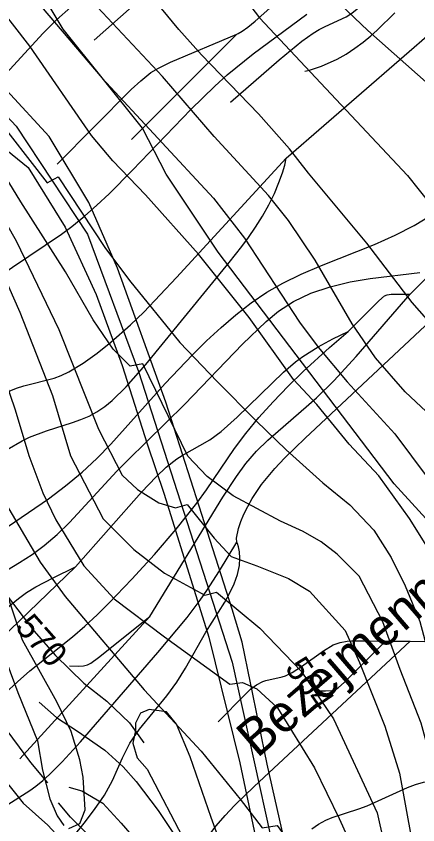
# Model space of a CAD drawing. Extents: x -709584 to -702006, y -1161789 to -1157496.
# Drawn here: x -707846 to -707683.9, y -1159256.1 to -1158929.8 of the extents above; entities that cross this region are included whole.
import ezdxf

# ---------------------------------------------------------------- set-up
doc = ezdxf.new("R2010")
doc.units = 0
for name, color, linetype in [('110_silnice II. třídy a III. třídy', 7, 'Continuous'), ('120_vrstevnice hlavní', 7, 'Continuous'), ('121_vrstevnice hlavní_popis', 7, 'Continuous'), ('122_vrstevnice základní', 7, 'Continuous'), ('408_BPEJ_linie', 7, 'Continuous'), ('411_akumulovaný odtok', 7, 'Continuous'), ('419_LPIS PB', 7, 'Continuous'), ('502_vodní tok_popis', 7, 'Continuous')]:
    doc.layers.add(name, color=color, linetype=linetype)

msp = doc.modelspace()

# ---------------------------------------------------------------- linework, layer by layer
at = {"layer": '110_silnice II. třídy a III. třídy'}
msp.add_lwpolyline([(-707891.2, -1158926.02), (-707845.98, -1158974.16), (-707817.26, -1159017.7), (-707796.68, -1159073.19), (-707758.86, -1159190.4), (-707734.44, -1159300.73), (-707726.3, -1159328.96), (-707710.98, -1159361.01), (-707689.44, -1159398.33), (-707672.68, -1159420.33), (-707591.22, -1159519.21), (-707503.14, -1159616.33), (-707475.85, -1159642.64), (-707378.49, -1159735.32), (-707320.09, -1159789.38), (-707255.46, -1159826.22), (-707200.25, -1159861.16), (-707169.1, -1159885.49), (-707119.45, -1159925.38), (-707100.71, -1159937.16)], dxfattribs=at)
at = {"layer": '120_vrstevnice hlavní'}
for points in [[(-707636.08, -1159108.46), (-707639.17, -1159101.31), (-707643.74, -1159093.3), (-707658.02, -1159076.3), (-707672.31, -1159061.02), (-707686.17, -1159045.3), (-707704.45, -1159021.3), (-707728.03, -1158993.16), (-707735.74, -1158983.3), (-707748.17, -1158969.16), (-707771.17, -1158945.3), (-707780.31, -1158935.15), (-707815.32, -1158892.58)], [(-707674.29, -1159261.8), (-707677.87, -1159232.35), (-707682.54, -1159215.05), (-707691.03, -1159193.35), (-707697.97, -1159174.23), (-707707.61, -1159155.78), (-707716.48, -1159146.83), (-707722.87, -1159141.85), (-707730.12, -1159137.73), (-707739.27, -1159133.61), (-707758.43, -1159123.31), (-707768.96, -1159115.58), (-707776.73, -1159107.32), (-707794.94, -1159070.03), (-707799.98, -1159071.07), (-707806.9, -1159064.2), (-707814.95, -1159052.25), (-707826.02, -1159032.96), (-707844.09, -1159004.73), (-707859.8, -1158979.14)], [(-707861.24, -1159145.22), (-707849.59, -1159163.75), (-707838.9, -1159177.82), (-707830.11, -1159187.78), (-707818.64, -1159198.87), (-707809.34, -1159206.24), (-707800.21, -1159214.99), (-707794.42, -1159223.01)]]:
    msp.add_lwpolyline(points, dxfattribs=at)
at = {"layer": '122_vrstevnice základní'}
for points in [[(-707764.89, -1158908.01), (-707747.74, -1158930.44), (-707688.02, -1158994.01), (-707659.88, -1159029.59), (-707651.45, -1159038.02), (-707642.17, -1159044.45), (-707634.17, -1159048.16), (-707609.88, -1159056.3), (-707603.14, -1159060.08), (-707600.08, -1159062.31), (-707598.37, -1159064.54), (-707597.01, -1159068.72), (-707596.76, -1159075.94), (-707598.68, -1159086.56), (-707601.19, -1159097.43), (-707602.86, -1159103.56), (-707605.81, -1159111.69)], [(-707662.93, -1159195.81), (-707670.93, -1159164.59), (-707677.53, -1159147.94), (-707687.22, -1159132.43), (-707699.69, -1159115.21), (-707711.62, -1159102.46), (-707724.6, -1159086.45), (-707734.03, -1159076.45), (-707752.03, -1159051.3), (-707772.46, -1159025.87), (-707793.74, -1159001.87), (-707807.03, -1158988.16), (-707815.6, -1158977.87), (-707840.46, -1158941.87), (-707860.6, -1158915.87)], [(-707843.6, -1158916.73), (-707811.32, -1158954.73), (-707766.31, -1159003.16), (-707753.88, -1159019.3), (-707731.6, -1159053.3), (-707724.17, -1159063.3), (-707712.45, -1159077.3), (-707693.17, -1159098.3), (-707673.44, -1159124.76), (-707665.99, -1159135.97), (-707660.78, -1159149.08), (-707655.03, -1159174.45)], [(-708042.18, -1158921.87), (-708027.33, -1158933.01), (-707999.9, -1158955.01), (-707985.18, -1158967.87), (-707963.04, -1158986.01), (-707952.04, -1158996.3), (-707943.89, -1159005.3), (-707939.87, -1159014.34), (-707935.04, -1159028.05), (-707930.67, -1159065.95), (-707929.33, -1159081), (-707926.38, -1159096.77), (-707921.37, -1159112.72), (-707913.95, -1159132.26), (-707898.64, -1159162.73), (-707882.13, -1159193.75), (-707869.39, -1159214.3), (-707855.28, -1159232.28), (-707843.15, -1159247.3)], [(-707833.26, -1159239.13), (-707840.08, -1159230.91), (-707851.96, -1159214.97), (-707871.68, -1159187.3), (-707882.53, -1159169.82), (-707893.61, -1159149.57), (-707904.3, -1159127.97), (-707913.2, -1159106.04), (-707918.05, -1159086.14), (-707920.74, -1159066.95), (-707921.64, -1159051.33), (-707922.01, -1159039.15), (-707922.89, -1159025.24), (-707925.46, -1159014.73), (-707935.61, -1158999.02), (-707949.32, -1158982.58), (-707958.89, -1158973.44), (-707981.32, -1158955.87), (-707999.9, -1158942.16), (-708020.33, -1158924.73)], [(-707645.44, -1159145), (-707649.59, -1159128.45), (-707658.45, -1159113.88), (-707666.17, -1159103.59), (-707676.17, -1159093.3), (-707689.02, -1159081.3), (-707701.02, -1159067.59), (-707710.45, -1159053.88), (-707725.31, -1159028.16), (-707736.03, -1159012.16), (-707744.17, -1159002.16), (-707766.03, -1158978.3), (-707786.89, -1158954.16), (-707813.17, -1158926.15)], [(-707714.88, -1158925.3), (-707704.03, -1158935.58), (-707668.74, -1158966.87), (-707650.59, -1158984.16), (-707624.45, -1159006.87), (-707611.88, -1159016.59), (-707592.73, -1159027.59), (-707586.59, -1159032.02), (-707582.02, -1159036.73), (-707567.73, -1159055.59), (-707560.16, -1159063.02), (-707553.88, -1159066.73), (-707544.73, -1159070.45), (-707535.59, -1159072.59), (-707524.16, -1159073.88), (-707499.59, -1159073.02), (-707489.87, -1159073.45)], [(-707855.53, -1158968.71), (-707833.47, -1158997.05), (-707828.99, -1158994.62), (-707810.15, -1159023.11), (-707800.29, -1159036.37), (-707779.89, -1159061.51), (-707764.85, -1159077.17), (-707749.18, -1159093.11), (-707737.08, -1159104.81), (-707722.22, -1159118.06), (-707711.33, -1159127), (-707701.6, -1159137.2), (-707694.68, -1159148.23), (-707688.96, -1159159.6), (-707683.07, -1159174.07), (-707665.46, -1159239.67)], [(-707867.75, -1158982.33), (-707845.96, -1159020.36), (-707828.75, -1159056.16)], [(-707876.88, -1158985.33), (-707865.64, -1159004.25), (-707855.31, -1159025.08), (-707844.58, -1159049.17), (-707831.3, -1159082.81), (-707824.02, -1159107.25), (-707810.82, -1159132.61), (-707798.57, -1159144.98), (-707786.15, -1159154.59), (-707769.85, -1159163.36), (-707765.2, -1159162.15)], [(-707886.99, -1158990.28), (-707879.04, -1159004.38), (-707869.7, -1159025.35), (-707858.82, -1159052.74), (-707846.38, -1159088.58), (-707840.83, -1159106.99), (-707835.29, -1159122.12), (-707829.93, -1159132.95), (-707818.68, -1159151.56), (-707806.43, -1159164.96), (-707786.09, -1159180.23), (-707759.76, -1159199.37)], [(-707898.3, -1158994.45), (-707889.48, -1159017.13), (-707879.4, -1159042.22), (-707870.23, -1159065.6), (-707861.97, -1159090.81), (-707857.98, -1159107.66), (-707851.23, -1159124.68), (-707836.26, -1159150.07), (-707826.25, -1159163.98), (-707794.33, -1159201.65), (-707771.35, -1159226.36), (-707755.65, -1159245.77), (-707746.68, -1159257.27), (-707740.67, -1159256.4), (-707729.8, -1159271.34), (-707715.51, -1159298.9), (-707703.93, -1159322.1), (-707687.5, -1159342.8), (-707674.05, -1159354.64), (-707659.74, -1159365.89), (-707631.31, -1159397.03), (-707621.2, -1159409.47), (-707587.64, -1159457.53), (-707575.99, -1159476.79)], [(-707828.75, -1159056.16), (-707812.81, -1159096.44), (-707803.22, -1159114.95), (-707797.01, -1159120.79), (-707788.38, -1159126.11), (-707781.66, -1159128.17)], [(-707781.66, -1159128.17), (-707777.01, -1159126.78), (-707766.1, -1159140.41), (-707759.19, -1159147.81), (-707748.85, -1159151.57), (-707736.08, -1159156.71), (-707727.63, -1159161.86), (-707713.19, -1159177.71), (-707707.47, -1159190.62), (-707697.25, -1159216.27), (-707691.35, -1159235.2), (-707686.42, -1159261.75), (-707682.74, -1159287.41), (-707679.44, -1159302.05), (-707674.64, -1159311.69), (-707670.32, -1159317.88), (-707664.28, -1159324.41), (-707651.85, -1159335.76), (-707639.94, -1159346.07), (-707632.35, -1159350.53), (-707628.04, -1159351.38)], [(-707765.2, -1159162.15), (-707747.6, -1159176.75), (-707731.04, -1159194.1), (-707717.91, -1159213.36), (-707700.25, -1159251.27), (-707695.21, -1159274.16), (-707689.83, -1159293.95), (-707684.63, -1159306.86), (-707677.89, -1159318.25), (-707669.6, -1159329.26), (-707653.73, -1159344.55), (-707644.02, -1159352.72), (-707632.46, -1159363.02), (-707624.01, -1159367.82), (-707618.77, -1159367.76)], [(-707759.76, -1159199.37), (-707754.6, -1159198.67), (-707748.84, -1159201.17), (-707740.56, -1159208.9), (-707725.54, -1159233.13), (-707715.68, -1159253.59), (-707702.77, -1159282.12), (-707691.35, -1159310.49), (-707678.57, -1159331.46), (-707663.56, -1159348.12), (-707651.96, -1159360.31), (-707640.05, -1159371.99), (-707598.28, -1159427.66), (-707592.42, -1159433.26), (-707587.08, -1159437.04), (-707582.43, -1159437.89), (-707579.16, -1159437.19)], [(-707836.68, -1159206.63), (-707829.78, -1159212.76), (-707821.18, -1159218.24), (-707810.16, -1159225.95), (-707802.76, -1159232.63), (-707797.59, -1159238.63), (-707788.63, -1159250.3), (-707776.82, -1159268.1)], [(-707824.68, -1159240.9), (-707819.47, -1159242.43), (-707811.04, -1159247.39), (-707803.57, -1159255.37), (-707791.51, -1159269.43), (-707742.74, -1159346.83), (-707719.71, -1159378.77), (-707683.61, -1159425.96), (-707661.04, -1159451.95)], [(-707843.15, -1159247.3), (-707833.18, -1159256.2), (-707823.72, -1159266.65), (-707806.81, -1159286.46), (-707795.28, -1159305.48), (-707779.16, -1159335.98), (-707766.92, -1159360.48), (-707750.91, -1159387.3), (-707719.07, -1159436.59), (-707708.22, -1159452.18), (-707702.37, -1159461.26)], [(-707672.53, -1159464.95), (-707681.95, -1159452.71), (-707746.6, -1159366.1), (-707755.61, -1159352.07), (-707769.94, -1159326.87), (-707780.28, -1159307.5), (-707793.09, -1159287.74), (-707801.88, -1159275.05), (-707824.07, -1159252.94), (-707828.92, -1159247.19)]]:
    msp.add_lwpolyline(points, dxfattribs=at)
at = {"layer": '408_BPEJ_linie'}
msp.add_lwpolyline([(-707645, -1159171.5), (-707693.5, -1159118.5), (-707764.5, -1159025), (-707785.5, -1158993.5), (-707795, -1158975), (-707827, -1158935), (-707854, -1158890), (-707891.5, -1158845), (-707907, -1158832), (-707935.5, -1158813), (-707948, -1158808), (-708010.5, -1158764), (-708023, -1158737), (-708035.5, -1158655.5), (-708032.5, -1158645.5), (-708035, -1158620.5), (-708037.78, -1158605.97)], dxfattribs=at)
at = {"layer": '411_akumulovaný odtok'}
for p, q in [((-707736.99, -1158987), (-707661.99, -1158922)), ((-707799.49, -1158979.5), (-707756.99, -1158937)), ((-707686.99, -1159042), (-707676.99, -1159032)), ((-707844.49, -1159229.5), (-707791.99, -1159172)), ((-707696.99, -1159182), (-707686.99, -1159182))]:
    msp.add_line(p, q, dxfattribs=at)
for points in [[(-707879.49, -1158979.5), (-707877.43, -1158978.31), (-707872.51, -1158974.65), (-707869.13, -1158971.81), (-707861.74, -1158964.95), (-707854.52, -1158957.65), (-707835.24, -1158936.7), (-707829.7, -1158931.18), (-707823.88, -1158926.07), (-707820.8, -1158923.76), (-707817.58, -1158921.68), (-707804.57, -1158914), (-707795.93, -1158907.91), (-707790.44, -1158903.46), (-707787.82, -1158901.11), (-707782.23, -1158895.54), (-707774.14, -1158887.03), (-707768.57, -1158881.85), (-707765.6, -1158879.61), (-707763, -1158877.99), (-707757.55, -1158874.95), (-707750.01, -1158870.03), (-707737.99, -1158861), (-707726.99, -1158852)], [(-707814.49, -1158939.5), (-707777.92, -1158906.85), (-707767.18, -1158896.81), (-707757.35, -1158886.24), (-707726.99, -1158852)], [(-707759.49, -1158964.5), (-707739.9, -1158947.42), (-707730.68, -1158939.91), (-707726.07, -1158936.63), (-707723.71, -1158935.17), (-707721.29, -1158933.87), (-707712.86, -1158930.02), (-707710.54, -1158928.57), (-707706.16, -1158925.08), (-707701.99, -1158921.13), (-707695.91, -1158914.81), (-707651.99, -1158867)], [(-707756.99, -1158937), (-707756.34, -1158936.78), (-707754.78, -1158935.84), (-707752.49, -1158934.23), (-707749.49, -1158931.84), (-707742.46, -1158925.5)], [(-707916.99, -1159072), (-707906.66, -1159067.84), (-707900.39, -1159064.89), (-707893.38, -1159061.16), (-707885.95, -1159056.84), (-707878.44, -1159052.19), (-707864.41, -1159042.9), (-707847.45, -1159030.99), (-707827.76, -1159017.68), (-707823.58, -1159014.67), (-707818.4, -1159010.5), (-707813.39, -1159006.07), (-707808.51, -1159001.46), (-707799, -1158991.88), (-707775.52, -1158967.4), (-707765.82, -1158957.95), (-707760.78, -1158953.44), (-707750.33, -1158945), (-707728.65, -1158929.01)], [(-707729.49, -1158952), (-707727.57, -1158951.54), (-707722.8, -1158949.93), (-707716.47, -1158947.11), (-707712.84, -1158945.05), (-707709.27, -1158942.7), (-707705.91, -1158940.21), (-707702.86, -1158937.72), (-707700.26, -1158935.35), (-707693.23, -1158928.42)], [(-707829.49, -1158989.5), (-707799.54, -1158959.42), (-707795.7, -1158955.8), (-707791.62, -1158952.54), (-707788.56, -1158950.71), (-707783.72, -1158948.34), (-707756.99, -1158937)], [(-707886.99, -1159092), (-707886.58, -1159091.5), (-707885.13, -1159090.82), (-707882.74, -1159090.09), (-707867.29, -1159087.06), (-707862.94, -1159086.1), (-707858.8, -1159084.97), (-707855.09, -1159083.66), (-707845.81, -1159079.87), (-707842.84, -1159078.96), (-707830.71, -1159075.83), (-707827.77, -1159074.76), (-707824.73, -1159073.33), (-707818.91, -1159069.8), (-707813.3, -1159065.71), (-707807.82, -1159061.3), (-707799.83, -1159054.31), (-707794.49, -1159049.2), (-707781.23, -1159035.23), (-707736.99, -1158987)], [(-707849.68, -1159104.59), (-707843.57, -1159101.2), (-707840.56, -1159099.71), (-707833.76, -1159097.12), (-707823.3, -1159093.8), (-707819.9, -1159092.57), (-707816.59, -1159091.16), (-707813.44, -1159089.49), (-707810.27, -1159087.34), (-707807.28, -1159084.87), (-707801.65, -1159079.35), (-707793.65, -1159070.27), (-707760.05, -1159029.14), (-707754.95, -1159022.76), (-707752.24, -1159019.11), (-707749.4, -1159014.96), (-707746.61, -1159010.49), (-707744.01, -1159005.88), (-707741.76, -1159001.3), (-707739.93, -1158996.9), (-707738.56, -1158993), (-707737.63, -1158989.87), (-707736.99, -1158987)], [(-707857.68, -1159141.39), (-707832.97, -1159124.49), (-707826.04, -1159119.36), (-707819.37, -1159113.8), (-707813.49, -1159108.27), (-707807.81, -1159102.45), (-707785.83, -1159077.97), (-707774.81, -1159066.38), (-707769.13, -1159060.81), (-707763.31, -1159055.43), (-707757.35, -1159050.3), (-707751.21, -1159045.51), (-707744.83, -1159041.18), (-707738.32, -1159037.47), (-707731.02, -1159033.94), (-707722.79, -1159030.39), (-707701.32, -1159021.88), (-707693.1, -1159018.15), (-707685.39, -1159014.17), (-707678.45, -1159010.09)], [(-707860.39, -1159159.76), (-707844.68, -1159150.23), (-707839.58, -1159146.94), (-707834.68, -1159143.39), (-707829.45, -1159138.93), (-707824.49, -1159134.1), (-707805.42, -1159113.42), (-707800.99, -1159108.89), (-707777.99, -1159086.32), (-707754.67, -1159062.12), (-707745.16, -1159053.02), (-707740.14, -1159048.84), (-707734.12, -1159044.9), (-707727.06, -1159041.51), (-707719.32, -1159038.93), (-707711.2, -1159037.03), (-707703.11, -1159035.65), (-707683.04, -1159033.21)], [(-707756.99, -1159142), (-707757.02, -1159140.41), (-707756.26, -1159136.51), (-707755.34, -1159133.73), (-707754.06, -1159130.71), (-707752.5, -1159127.58), (-707750.75, -1159124.47), (-707747.04, -1159118.82), (-707741.67, -1159112.3), (-707737.71, -1159108.14), (-707729.41, -1159100.12), (-707661.99, -1159037)], [(-707791.99, -1159172), (-707762.56, -1159123.84), (-707757.14, -1159115.55), (-707753.26, -1159110.24), (-707749, -1159105.35), (-707744.37, -1159100.86), (-707724.81, -1159083.78), (-707717.77, -1159076.86), (-707708.81, -1159067.05), (-707686.99, -1159042)], [(-707711.99, -1159057), (-707699.66, -1159044.6), (-707697.33, -1159042.68), (-707696.3, -1159042.23), (-707694.65, -1159041.96), (-707686.99, -1159042)], [(-707850.37, -1159202.9), (-707845.48, -1159198.35), (-707840.45, -1159193.98), (-707823.25, -1159180.27), (-707818.24, -1159175.89), (-707813.35, -1159171.34), (-707808.58, -1159166.64), (-707799.27, -1159156.96), (-707790.2, -1159147.01), (-707781.42, -1159136.8), (-707773.08, -1159126.26), (-707769.17, -1159120.85), (-707757.84, -1159104.28), (-707753.35, -1159098.22), (-707748.08, -1159091.76), (-707742.28, -1159085.33), (-707736.2, -1159079.07), (-707730.15, -1159073.21), (-707719.51, -1159063.46), (-707711.99, -1159057)], [(-707821.99, -1159152), (-707795.41, -1159121.87), (-707789.55, -1159115.67), (-707785.47, -1159111.8), (-707781.1, -1159108.37), (-707778.94, -1159107), (-707767.78, -1159100.73), (-707763.2, -1159097.36), (-707756.74, -1159091.65), (-707738.04, -1159073.37), (-707733.25, -1159069.28), (-707730.29, -1159067.12), (-707724.07, -1159063.25), (-707718.15, -1159060.03), (-707711.99, -1159057)], [(-707879.49, -1159279.5), (-707871.24, -1159269.62), (-707865.23, -1159262.7), (-707859.03, -1159256.04), (-707856.14, -1159253.22), (-707853.48, -1159250.89), (-707850.78, -1159248.8), (-707840.52, -1159242.21), (-707838.02, -1159240.46), (-707835.24, -1159238.24), (-707832.57, -1159235.85), (-707827.46, -1159230.74), (-707820.08, -1159222.64), (-707788.78, -1159186.5), (-707776.94, -1159172.44), (-707771.72, -1159165.47), (-707769.02, -1159161.52), (-707763.9, -1159153.53), (-707756.99, -1159142)], [(-707827.45, -1159266.52), (-707818.58, -1159255.44), (-707814.32, -1159249.88), (-707810.41, -1159244.13), (-707808.67, -1159241.14), (-707807.16, -1159238.16), (-707803.08, -1159229.02), (-707800.06, -1159223.11), (-707796.2, -1159217.45), (-707785.2, -1159203.98), (-707781.22, -1159198.46), (-707777.72, -1159192.81), (-707769.47, -1159178.35), (-707761.81, -1159166.19), (-707759.77, -1159162.54), (-707758, -1159158.79), (-707756.65, -1159155.06), (-707755.87, -1159151.47), (-707755.68, -1159148.51), (-707755.85, -1159145.94), (-707756.21, -1159143.9), (-707756.63, -1159142.54), (-707756.99, -1159142)], [(-707989.49, -1159324.5), (-707987.25, -1159322.35), (-707981.86, -1159316.53), (-707974.87, -1159308.28), (-707971.27, -1159303.63), (-707960.42, -1159288.01), (-707957.58, -1159284.34), (-707954.57, -1159280.79), (-707948.18, -1159273.92), (-707931.35, -1159257.31), (-707821.99, -1159152)], [(-707904.49, -1159214.5), (-707887.23, -1159203.66), (-707883.9, -1159201.36), (-707880.75, -1159198.92), (-707877.88, -1159196.21), (-707875.61, -1159193.41), (-707871.27, -1159187.57), (-707867.09, -1159183.19), (-707857.85, -1159175.09), (-707845.09, -1159164.73), (-707841.76, -1159162.37), (-707838.04, -1159160.11), (-707831.02, -1159156.43), (-707821.99, -1159152)], [(-707686.99, -1159182), (-707674.38, -1159182.2), (-707670.76, -1159181.89), (-707668.55, -1159181.32), (-707667.55, -1159180.84), (-707665.75, -1159179.37), (-707664.17, -1159177.49), (-707660.55, -1159172.39), (-707659.1, -1159170.62), (-707657.59, -1159169.36), (-707656.8, -1159169.07), (-707655.23, -1159169.27), (-707651.65, -1159170.81), (-707648.27, -1159171.58), (-707643.15, -1159171.95), (-707631.99, -1159172)], [(-707824.49, -1159192), (-707820.8, -1159192.05), (-707818.87, -1159191.91), (-707817.17, -1159191.55), (-707815.82, -1159190.89), (-707812.7, -1159188.63), (-707791.99, -1159172)], [(-707776.99, -1159284.5), (-707776.93, -1159281.04), (-707776.04, -1159276.13), (-707775.05, -1159273), (-707773.72, -1159269.78), (-707772.15, -1159266.61), (-707768.69, -1159260.94), (-707765.29, -1159256.5), (-707761.7, -1159252.29), (-707757.88, -1159248.29), (-707749.89, -1159240.61), (-707686.99, -1159182)], [(-707764.49, -1159214.5), (-707753.62, -1159203.45), (-707751.36, -1159201.41), (-707749.01, -1159199.62), (-707746.49, -1159198.23), (-707745.25, -1159197.79), (-707738.65, -1159196.32), (-707737.36, -1159195.91), (-707734.65, -1159194.66), (-707730.78, -1159192.21), (-707721.96, -1159185.84), (-707718.05, -1159183.51), (-707715.28, -1159182.52), (-707712.35, -1159182.03), (-707710.63, -1159181.9), (-707704.64, -1159181.83), (-707696.99, -1159182)], [(-707724.49, -1159202), (-707721.11, -1159202.08), (-707718.52, -1159201.91), (-707717.18, -1159201.54), (-707716.05, -1159200.86), (-707713.47, -1159198.55), (-707696.99, -1159182)], [(-707726.68, -1159257.77), (-707723.96, -1159255.88), (-707721.09, -1159254.28), (-707718.52, -1159253.18), (-707707.68, -1159249.68), (-707704.38, -1159248.43), (-707688.13, -1159241.1), (-707684.86, -1159239.84), (-707681.55, -1159238.83), (-707678.48, -1159238.21), (-707675.41, -1159237.87), (-707672.35, -1159237.77), (-707669.36, -1159237.92), (-707666.31, -1159238.32), (-707663.11, -1159238.99), (-707655.13, -1159241.06), (-707652.56, -1159241.36), (-707650.34, -1159241.29), (-707648.27, -1159240.92), (-707645.72, -1159239.98), (-707643.74, -1159238.83), (-707642.46, -1159237.76), (-707641.99, -1159237)]]:
    msp.add_lwpolyline(points, dxfattribs=at)
at = {"layer": '419_LPIS PB'}
for points in [[(-707730.73, -1159293.62), (-707744.74, -1159231.61), (-707754.77, -1159182.35), (-707758.78, -1159169), (-707772.1, -1159127.5), (-707785.6, -1159085.5), (-707805.16, -1159031.52), (-707816.67, -1159004.91), (-707832.69, -1158978.3), (-707849.71, -1158959.72), (-707876.74, -1158931.1), (-707895.26, -1158911.32)], [(-707849.71, -1158983.82), (-707841.2, -1158990.85), (-707826.18, -1159014.95), (-707813.67, -1159042.06), (-707803.16, -1159070.68), (-707793.15, -1159102.32), (-707786.29, -1159122.65), (-707768.27, -1159180.39), (-707755.76, -1159231.11), (-707745.24, -1159280.82)], [(-707824.7, -1159257.6), (-707820.3, -1159255.5), (-707818.2, -1159250.1), (-707818.9, -1159236.9), (-707820.3, -1159229.9), (-707823.8, -1159218.4), (-707829.6, -1159206.5), (-707843.5, -1159181.6), (-707880.71, -1159070.37)], [(-707854.7, -1159177.7), (-707845.3, -1159202.7), (-707837.4, -1159222.2), (-707835.3, -1159234.1), (-707832.4, -1159245.6), (-707829.4, -1159252.4), (-707826.8, -1159256.4)], [(-707760.76, -1159271.28), (-707767.27, -1159253.2), (-707775.78, -1159228.6), (-707781.28, -1159215.54), (-707785.29, -1159210.52), (-707792.3, -1159209.52), (-707795.8, -1159211.02), (-707797.8, -1159215.04), (-707797.8, -1159218), (-707798.9, -1159223.1), (-707797.1, -1159229), (-707793.1, -1159233.7), (-707777.4, -1159263.7)]]:
    msp.add_lwpolyline(points, dxfattribs=at)

# ---------------------------------------------------------------- texts
at = {"layer": '121_vrstevnice hlavní_popis'}
for s, rotation, p in [('570', 311.4308, (-707846.81, -1159176.56)), ('564', 304.7713, (-707737.8, -1159192.8))]:
    msp.add_text(s, height=10, rotation=rotation, dxfattribs=at).set_placement(p)
at = {"layer": '502_vodní tok_popis'}
msp.add_text('Bezejmenný vodní tok 01 (Lesy ČR, s.p.)', height=15, rotation=40.7601, dxfattribs=at).set_placement((-707748.73, -1159229.46))

doc.saveas('drawing.dxf')
